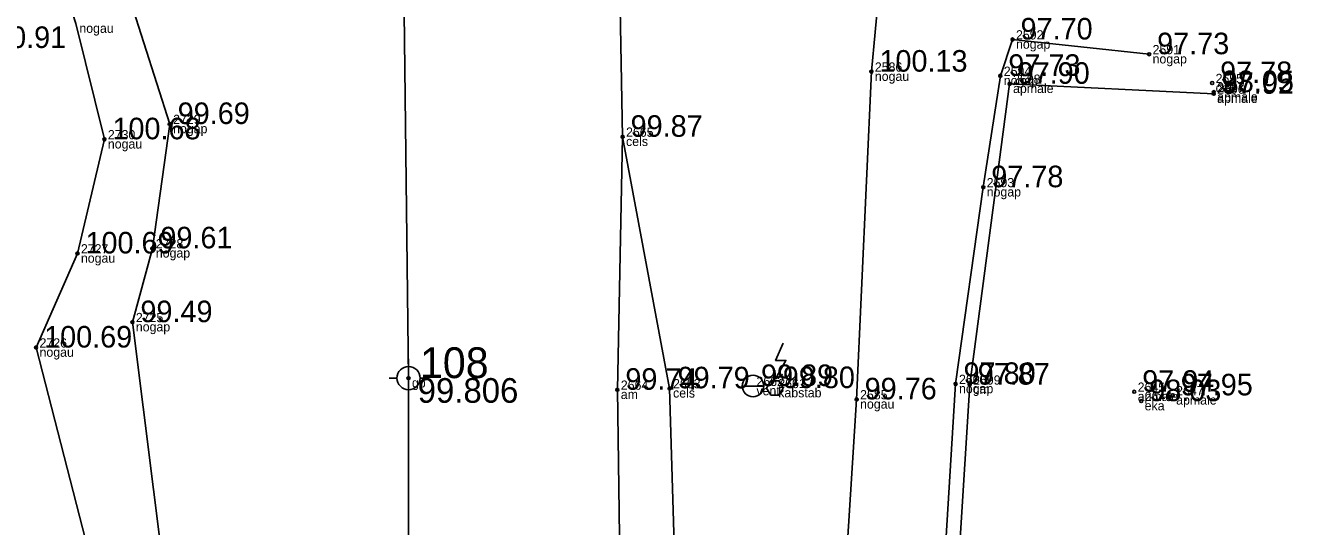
# Model space of a CAD drawing. Extents: x 614911 to 615803, y 262110 to 264311.
# Drawn here: x 615613.61 to 615654.79, y 263768.53 to 263784.81 of the extents above; entities that cross this region are included whole.
import ezdxf

# ---------------------------------------------------------------- set-up
doc = ezdxf.new("R2010")
doc.units = 0
for name, color, linetype in [('Level 12', 7, 'Continuous'), ('Level 19', 7, 'Continuous'), ('Level 31', 7, 'Continuous'), ('Level 37', 7, 'Continuous'), ('Level 53', 7, 'Continuous'), ('Level 54', 7, 'Continuous'), ('Level 57', 7, 'Continuous'), ('Level 58', 7, 'Continuous')]:
    doc.layers.add(name, color=color, linetype=linetype)

msp = doc.modelspace()

# ---------------------------------------------------------------- linework, layer by layer
at = {"layer": 'Level 12'}
for p, q in [((615637.986, 263773.331), (615638.227, 263773.47)), ((615636.903, 263773.098), (615637.605, 263773.098))]:
    msp.add_line(p, q, dxfattribs=at)
for points in [[(615638.235, 263774.493), (615637.986, 263773.93), (615638.322, 263773.93), (615637.986, 263773.331)], [(615637.964, 263773.601), (615637.986, 263773.331)]]:
    msp.add_lwpolyline(points, dxfattribs=at)
msp.add_lwpolyline([(615637.83, 263772.801), (615638.096, 263772.801), (615638.229, 263773.031), (615638.096, 263773.262), (615637.83, 263773.262), (615637.697, 263773.031)], close=True, dxfattribs=at)
msp.add_circle((615637.254, 263773.098), 0.351, dxfattribs=at)
at = {"layer": 'Level 19'}
for p, q in [((615626.06, 263773.73), (615626.06, 263773.98)), ((615626.06, 263773.73), (615626.06, 263773.98)), ((615625.435, 263773.355), (615625.685, 263773.355)), ((615625.435, 263773.355), (615625.685, 263773.355)), ((615626.435, 263773.355), (615626.685, 263773.355)), ((615626.435, 263773.355), (615626.685, 263773.355)), ((615626.06, 263772.73), (615626.06, 263772.98)), ((615626.06, 263772.73), (615626.06, 263772.98))]:
    msp.add_line(p, q, dxfattribs=at)
for radius in [0.375, 0.375, 0.05, 0.05]:
    msp.add_circle((615626.06, 263773.355), radius, dxfattribs=at)
at = {"layer": 'Level 31'}
for points in [[(615634.983, 263742.124), (615637.151, 263741.18), (615639.129, 263741.365), (615639.417, 263742.418), (615639.55, 263747.26), (615639.824, 263760.15), (615640.622, 263772.665), (615641.102, 263783.306), (615641.462, 263787.159), (615642.356, 263789.074), (615643.885, 263789.526), (615651.852, 263789.078)], [(615614.813, 263786.223), (615615.252, 263784.867), (615616.178, 263781.11), (615615.302, 263777.403), (615613.958, 263774.348), (615616.068, 263766.131), (615618.488, 263761.449), (615618.408, 263755.418), (615617.799, 263750.991), (615617.82, 263744.201), (615617.255, 263741.211)], [(615617.255, 263741.211), (615619.81, 263743.966), (615619.642, 263750.955), (615621.005, 263755.429), (615620.421, 263761.627), (615618.119, 263766.983), (615617.088, 263775.172), (615617.737, 263777.569), (615618.299, 263781.606), (615617.041, 263785.567), (615614.813, 263786.223)], [(615650.127, 263783.872), (615645.689, 263784.351), (615645.292, 263783.17), (615644.737, 263779.553), (615643.836, 263773.165), (615643.021, 263759.915), (615642.305, 263748.69), (615642.116, 263742.526), (615641.655, 263741.131), (615640.666, 263740.333), (615639.015, 263739.933), (615634.983, 263742.124)]]:
    msp.add_lwpolyline(points, dxfattribs=at)
at = {"layer": 'Level 37'}
for points in [[(615599.876, 263919.455), (615604.05, 263925.447), (615607.684, 263927.303), (615608.393, 263927.682), (615609.17, 263927.713), (615613.447, 263925.367), (615619.425, 263922.192), (615624.751, 263919.238), (615626.516, 263914.529), (615627.589, 263910.62), (615627.021, 263902.326), (615625.968, 263885.28), (615625.441, 263867.412), (615625.701, 263849.423), (615625.695, 263830.774), (615625.747, 263806.701), (615625.922, 263785.222), (615626.06, 263773.355), (615626.048, 263762.098), (615626.08, 263750.419), (615624.574, 263747.097), (615620.445, 263741.787), (615617.245, 263740.487), (615614.217, 263740.593)], [(615633.017, 263781.192), (615632.562, 263806.29), (615632.287, 263829.055), (615632.264, 263849.326), (615632.338, 263865.829), (615632.663, 263885.458)], [(615652.226, 263782.589), (615645.593, 263782.912), (615644.296, 263773.143), (615643.468, 263759.865), (615642.873, 263748.521), (615642.461, 263741.337), (615642.486, 263740.4)], [(615647.16, 263734.641), (615647.309, 263739.2), (615643.255, 263740.347), (615642.486, 263740.4), (615641.175, 263739.63), (615639.192, 263739.55), (615636.348, 263740.293), (615634.431, 263741.866), (615632.666, 263744.984), (615633.083, 263756.34), (615632.847, 263772.977), (615633.017, 263781.192)], [(615633.017, 263781.192), (615634.544, 263773.023), (615635.045, 263756.08), (615634.375, 263744.29), (615634.431, 263741.866)]]:
    msp.add_lwpolyline(points, dxfattribs=at)
at = {"layer": 'Level 57'}
for centre in [(615645.689, 263784.351), (615650.127, 263783.872), (615641.102, 263783.306), (615645.292, 263783.17), (615645.593, 263782.912), (615652.174, 263782.935), (615652.226, 263782.589), (615652.227, 263782.641), (615618.299, 263781.606), (615616.178, 263781.11), (615633.017, 263781.192), (615644.737, 263779.553), (615615.302, 263777.403), (615617.737, 263777.569), (615617.088, 263775.172), (615613.958, 263774.348), (615632.847, 263772.977), (615634.544, 263773.023), (615643.836, 263773.165), (615644.296, 263773.143), (615649.642, 263772.912), (615650.893, 263772.795), (615640.622, 263772.665), (615649.87, 263772.608)]:
    msp.add_circle(centre, 0.05, dxfattribs=at)
at = {"layer": 'Level 58'}
for centre in [(615645.689, 263784.351), (615650.127, 263783.872), (615641.102, 263783.306), (615645.292, 263783.17), (615645.593, 263782.912), (615652.174, 263782.935), (615652.226, 263782.589), (615652.227, 263782.641), (615618.299, 263781.606), (615616.178, 263781.11), (615633.017, 263781.192), (615644.737, 263779.553), (615615.302, 263777.403), (615617.737, 263777.569), (615617.088, 263775.172), (615613.958, 263774.348), (615632.847, 263772.977), (615634.544, 263773.023), (615643.836, 263773.165), (615644.296, 263773.143), (615649.642, 263772.912), (615650.893, 263772.795), (615640.622, 263772.665), (615649.87, 263772.608)]:
    msp.add_circle(centre, 0.05, dxfattribs=at)

# ---------------------------------------------------------------- texts
at = {"layer": 'Level 19'}
for s, height, p in [(' 108', 1, (615626.06, 263773.355)), (' 108', 1, (615626.06, 263773.355)), (' 99.806', 0.8, (615626.06, 263772.555)), (' 99.806', 0.8, (615626.06, 263772.555))]:
    msp.add_text(s, height=height, dxfattribs=at).set_placement(p)
at = {"layer": 'Level 53'}
for s, p in [(' nogau', (615615.252, 263784.567)), (' nogap', (615645.689, 263784.051)), (' nogap', (615650.127, 263783.572)), (' nogau', (615641.102, 263783.006)), (' nogap', (615645.292, 263782.87)), (' apmale', (615645.593, 263782.612)), (' cm', (615652.174, 263782.635)), (' apmale', (615652.226, 263782.289)), (' apmale', (615652.227, 263782.341)), (' nogap', (615618.299, 263781.306)), (' cels', (615633.017, 263780.892)), (' nogau', (615616.178, 263780.81)), (' nogap', (615644.737, 263779.253)), (' nogap', (615617.737, 263777.269)), (' nogau', (615615.302, 263777.103)), (' nogap', (615617.088, 263774.872)), (' nogau', (615613.958, 263774.048)), (' gp', (615626.06, 263773.055)), (' gp', (615626.06, 263773.055)), (' am', (615632.847, 263772.677)), (' cels', (615634.544, 263772.723)), (' vent', (615637.254, 263772.798)), (' kabstab', (615637.963, 263772.731)), (' nogap', (615643.836, 263772.865)), (' cm', (615644.296, 263772.843)), (' apmale', (615649.642, 263772.612)), (' nogau', (615640.622, 263772.365)), (' eka', (615649.87, 263772.308)), (' apmale', (615650.893, 263772.495))]:
    msp.add_text(s, height=0.3, dxfattribs=at).set_placement(p)
at = {"layer": 'Level 54'}
for s, p in [(' 2592', (615645.689, 263784.351)), (' 2591', (615650.127, 263783.872)), (' 2586', (615641.102, 263783.306)), (' 2594', (615645.292, 263783.17)), (' 2598', (615645.593, 263782.912)), (' 2595', (615652.174, 263782.935)), (' 2596', (615652.226, 263782.589)), (' 2597', (615652.227, 263782.641)), (' 2729', (615618.299, 263781.606)), (' 2665', (615633.017, 263781.192)), (' 2730', (615616.178, 263781.11)), (' 2593', (615644.737, 263779.553)), (' 2728', (615617.737, 263777.569)), (' 2727', (615615.302, 263777.403)), (' 2725', (615617.088, 263775.172)), (' 2726', (615613.958, 263774.348)), (' 2664', (615632.847, 263772.977)), (' 2663', (615634.544, 263773.023)), (' 2662', (615637.254, 263773.098)), (' 2661', (615637.963, 263773.031)), (' 2600', (615643.836, 263773.165)), (' 2599', (615644.296, 263773.143)), (' 2585', (615640.622, 263772.665)), (' 2645', (615649.642, 263772.912)), (' 2646', (615649.87, 263772.608)), (' 2647', (615650.893, 263772.795))]:
    msp.add_text(s, height=0.3, dxfattribs=at).set_placement(p)
at = {"layer": 'Level 58'}
for s, p in [(' 100.91', (615611.812, 263784.075)), (' 97.70', (615645.689, 263784.351)), (' 97.73', (615650.127, 263783.872)), (' 100.13', (615641.102, 263783.306)), (' 97.73', (615645.292, 263783.17)), (' 97.90', (615645.593, 263782.912)), (' 97.78', (615652.174, 263782.935)), (' 97.92', (615652.226, 263782.589)), (' 98.05', (615652.227, 263782.641)), (' 99.69', (615618.299, 263781.606)), (' 99.87', (615633.017, 263781.192)), (' 100.68', (615616.178, 263781.11)), (' 97.78', (615644.737, 263779.553)), (' 99.61', (615617.737, 263777.569)), (' 100.69', (615615.302, 263777.403)), (' 99.49', (615617.088, 263775.172)), (' 100.69', (615613.958, 263774.348)), (' 99.74', (615632.847, 263772.977)), (' 99.79', (615634.544, 263773.023)), (' 99.89', (615637.254, 263773.098)), (' 99.80', (615637.963, 263773.031)), (' 97.80', (615643.836, 263773.165)), (' 97.87', (615644.296, 263773.143)), (' 99.76', (615640.622, 263772.665)), (' 97.94', (615649.642, 263772.912)), (' 98.03', (615649.87, 263772.608)), (' 97.95', (615650.893, 263772.795))]:
    msp.add_text(s, height=0.7, dxfattribs=at).set_placement(p)

doc.saveas('drawing.dxf')
